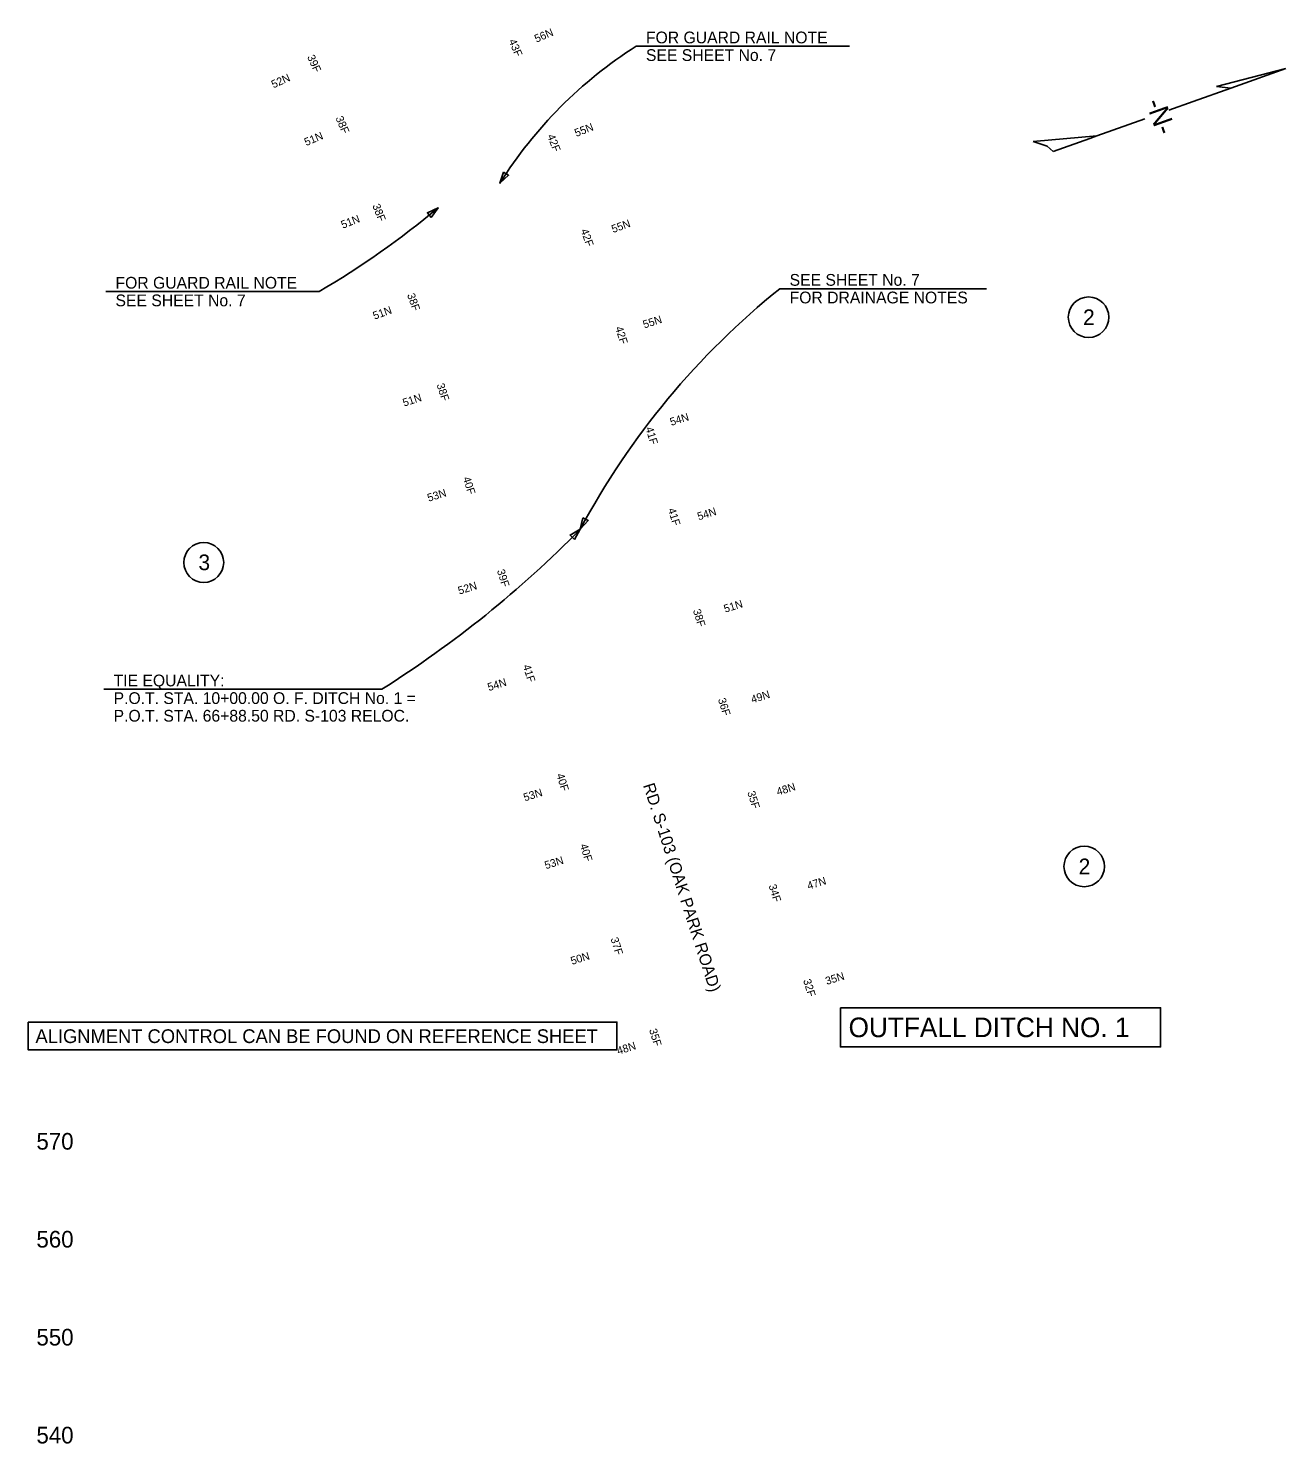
# Model space of a CAD drawing. Extents: x 1964849 to 1967422, y 1116563 to 1122210.
# Drawn here: x 1965762 to 1966404, y 1121475 to 1122198 of the extents above; entities that cross this region are included whole.
import ezdxf

# ---------------------------------------------------------------- set-up
doc = ezdxf.new("R2010")
doc.units = 0
for name, color, linetype in [('RD_DDB_Profile_Elev', 7, 'Continuous'), ('RD_EX_DV_TX_Prop', 7, 'Continuous'), ('RD_EX_Misc', 7, 'Continuous'), ('RD_HC_Data', 7, 'Continuous'), ('RD_PD_TX_CstnLmt', 7, 'Continuous'), ('RD_Sketch1', 7, 'Continuous'), ('RD_TX_Drainage', 7, 'Continuous'), ('RD_TX_Misc1', 7, 'Continuous'), ('RD_TX_Misc2', 7, 'Continuous'), ('RD_TX_RoadID', 7, 'Continuous')]:
    doc.layers.add(name, color=color, linetype=linetype)

msp = doc.modelspace()

# ---------------------------------------------------------------- linework, layer by layer
at = {"layer": 'RD_EX_DV_TX_Prop'}
for centre, radius in [((1966303, 1122050.52), 10.35), ((1965851.32, 1121925.33), 10.18), ((1966300.75, 1121770.15), 10.35)]:
    msp.add_circle(centre, radius, dxfattribs=at)
at = {"layer": 'RD_EX_Misc'}
for p, q in [((1966368.2, 1122168.4), (1966403.6, 1122177.49)), ((1966403.6, 1122177.49), (1966375.68, 1122167.53)), ((1966375.68, 1122167.53), (1966368.2, 1122168.4)), ((1966375.68, 1122167.53), (1966356.33, 1122160.63)), ((1966356.33, 1122160.63), (1966343.99, 1122156.23)), ((1966331.68, 1122151.83), (1966307.28, 1122143.13)), ((1966274.62, 1122140.24), (1966307.28, 1122143.13)), ((1966303.59, 1122141.81), (1966284.89, 1122135.15)), ((1966307.28, 1122143.13), (1966303.59, 1122141.81))]:
    msp.add_line(p, q, dxfattribs=at)
msp.add_lwpolyline([(1966284.89, 1122135.15), (1966281.88, 1122137.83), (1966274.62, 1122140.24)], dxfattribs=at)
at = {"layer": 'RD_HC_Data'}
msp.add_line((1965942.2, 1121860.58), (1965800.31, 1121860.58), dxfattribs=at)
msp.add_lwpolyline([(1966040.58, 1121937.1), (1966043.53, 1121942.33), (1966038.36, 1121939.27)], close=True, dxfattribs=at)
msp.add_arc((1965643.51, 1122334.48), 560.18, 302.2228, 315.56909, dxfattribs=at)
at = {"layer": 'RD_Sketch1'}
msp.add_lwpolyline([(1965761.78, 1121690.72), (1966062.2, 1121690.72), (1966062.2, 1121676.46), (1965761.78, 1121676.46)], close=True, dxfattribs=at)
at = {"layer": 'RD_TX_Drainage'}
msp.add_line((1966250.88, 1122065.1), (1966145.38, 1122065.1), dxfattribs=at)
msp.add_lwpolyline([(1966044.9, 1121948.17), (1966043.53, 1121942.33), (1966047.63, 1121946.7)], close=True, dxfattribs=at)
msp.add_arc((1966395.59, 1121753.89), 399.32, 128.79831, 151.84205, dxfattribs=at)
at = {"layer": 'RD_TX_Misc1'}
for p, q in [((1966180.98, 1122188.85), (1966072.05, 1122188.85)), ((1965910.21, 1122063.62), (1965801.28, 1122063.62))]:
    msp.add_line(p, q, dxfattribs=at)
for points in [[(1966004.28, 1122124.63), (1966002.53, 1122118.89), (1966006.92, 1122122.99)], [(1965967.47, 1122101.47), (1965970.92, 1122106.38), (1965965.48, 1122103.86)]]:
    msp.add_lwpolyline(points, close=True, dxfattribs=at)
for centre, radius, start, end in [((1966190.3, 1122001.84), 221.27, 122.30524, 148.05938), ((1965679.91, 1122455.07), 454.17, 300.46957, 309.84733)]:
    msp.add_arc(centre, radius, start, end, dxfattribs=at)
at = {"layer": 'RD_TX_Misc2'}
msp.add_lwpolyline([(1966176.29, 1121698), (1966339.73, 1121698), (1966339.73, 1121678), (1966176.29, 1121678)], close=True, dxfattribs=at)

# ---------------------------------------------------------------- texts
at = {"layer": 'RD_DDB_Profile_Elev'}
for s, p in [('570', (1965765.92, 1121625.58)), ('560', (1965765.92, 1121575.58)), ('550', (1965765.92, 1121525.58)), ('540', (1965765.92, 1121475.58))]:
    msp.add_text(s, height=8.5, dxfattribs=at).set_placement(p)
at = {"layer": 'RD_EX_DV_TX_Prop'}
for s, p in [('2', (1966300.16, 1122046.53)), ('3', (1965848.62, 1121921.4)), ('2', (1966297.91, 1121766.16))]:
    msp.add_text(s, height=8, dxfattribs=at).set_placement(p)
at = {"layer": 'RD_EX_Misc'}
msp.add_text('-N-', height=10, rotation=289.63025, dxfattribs=at).set_placement((1966332.02, 1122160.22))
at = {"layer": 'RD_HC_Data'}
for s, p in [('TIE EQUALITY:', (1965805.31, 1121862.08)), ('P.O.T. STA. 10+00.00 O. F. DITCH No. 1 =', (1965805.31, 1121853.08)), ('P.O.T. STA. 66+88.50 RD. S-103 RELOC.', (1965805.31, 1121844.08))]:
    msp.add_text(s, height=6, dxfattribs=at).set_placement(p)
at = {"layer": 'RD_PD_TX_CstnLmt'}
for s, rotation, p in [('43F', 293.11766, (1966006.89, 1122191.58)), ('39F', 294.36016, (1965904.02, 1122183.44)), ('38F', 293.11766, (1965918.52, 1122152.22)), ('42F', 291.36766, (1966026.57, 1122143.09)), ('38F', 291.36766, (1965937.32, 1122107.54)), ('42F', 289.61766, (1966043.65, 1122094.86)), ('38F', 289.61766, (1965955.05, 1122061.99)), ('42F', 287.86766, (1966061.28, 1122045.15)), ('38F', 287.86766, (1965970.15, 1122016.08)), ('41F', 287.35688, (1966076.74, 1121993.87)), ('41F', 287.35688, (1966076.74, 1121993.87)), ('40F', 287.35688, (1965983.54, 1121968.45)), ('41F', 287.35688, (1966088.2, 1121952.43)), ('39F', 287.35688, (1966000.94, 1121921.18)), ('38F', 287.35688, (1966100.98, 1121900.85)), ('41F', 287.35688, (1966014.15, 1121872.54)), ('36F', 287.35688, (1966113.76, 1121855.45)), ('40F', 287.35688, (1966031.28, 1121816.94)), ('35F', 287.35688, (1966128.74, 1121807.98)), ('40F', 287.35688, (1966043.3, 1121781.03)), ('34F', 287.35688, (1966139.61, 1121760.37)), ('37F', 287.35688, (1966058.93, 1121733.29)), ('32F', 287.35688, (1966157.23, 1121712.02)), ('35F', 287.35688, (1966078.61, 1121686.71))]:
    msp.add_text(s, height=4, rotation=rotation, dxfattribs=at).set_placement(p)
at = {"layer": 'RD_Sketch1'}
msp.add_text('ALIGNMENT CONTROL CAN BE FOUND ON REFERENCE SHEET', height=7, dxfattribs=at).set_placement((1965765.43, 1121680))
at = {"layer": 'RD_TX_Drainage'}
for s, rotation, p in [('56N', 23.11766, (1966021.17, 1122190.67)), ('52N', 24.36016, (1965886.92, 1122167.33)), ('55N', 21.36766, (1966041.53, 1122142.55)), ('51N', 23.11766, (1965903.66, 1122137.87)), ('51N', 21.36766, (1965922.31, 1122095.68)), ('55N', 19.61766, (1966060.29, 1122093.5)), ('51N', 19.61766, (1965938.5, 1122049.26)), ('55N', 17.86766, (1966076.24, 1122044.77)), ('51N', 17.86766, (1965953.62, 1122004.86)), ('54N', 17.35688, (1966090.01, 1121995.04)), ('53N', 17.35688, (1965966.16, 1121956.3)), ('54N', 17.35688, (1966103.99, 1121946.8)), ('52N', 17.35688, (1965981.82, 1121908.9)), ('51N', 17.35688, (1966117.49, 1121899.66)), ('54N', 17.35688, (1965996.89, 1121859.63)), ('49N', 17.35688, (1966131.35, 1121853.38)), ('53N', 17.35688, (1966015.23, 1121803.35)), ('48N', 17.35688, (1966144.4, 1121806.27)), ('53N', 17.35688, (1966026.01, 1121768.69)), ('47N', 17.35688, (1966160.05, 1121758.24)), ('50N', 17.35688, (1966039.34, 1121719.88)), ('35N', 17.35688, (1966169.35, 1121709.62)), ('48N', 17.35688, (1966062.95, 1121674))]:
    msp.add_text(s, height=4, rotation=rotation, dxfattribs=at).set_placement(p)
for s, p in [('SEE SHEET No. 7', (1966150.38, 1122066.6)), ('FOR DRAINAGE NOTES', (1966150.38, 1122057.6))]:
    msp.add_text(s, height=6, dxfattribs=at).set_placement(p)
at = {"layer": 'RD_TX_Misc1'}
for s, p in [('FOR GUARD RAIL NOTE', (1966077.05, 1122190.35)), ('SEE SHEET No. 7', (1966077.05, 1122181.35)), ('FOR GUARD RAIL NOTE', (1965806.28, 1122065.12)), ('SEE SHEET No. 7', (1965806.28, 1122056.12))]:
    msp.add_text(s, height=6, dxfattribs=at).set_placement(p)
at = {"layer": 'RD_TX_Misc2'}
msp.add_text('OUTFALL DITCH NO. 1', height=10, dxfattribs=at).set_placement((1966180.48, 1121683))
at = {"layer": 'RD_TX_RoadID'}
msp.add_text('RD. S-103 (OAK PARK ROAD)', height=6, rotation=287.92976, dxfattribs=at).set_placement((1966075.5, 1121811.59))

doc.saveas('drawing.dxf')
